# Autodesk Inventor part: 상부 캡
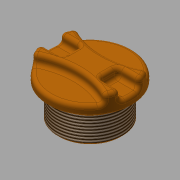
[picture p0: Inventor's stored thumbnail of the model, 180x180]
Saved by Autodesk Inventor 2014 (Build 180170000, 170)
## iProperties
Created: 2016-09
Part Number: 상부 캡
Material: ABS 플라스틱
Document SubType Name: Modeling
Designer: mduedu
Density: 1.493 g/cm^3
Appearance: 주황색
Author: mduedu
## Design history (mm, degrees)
sketch "스케치1"
  geometry: C1 r 22.5 at (0, 0); 1 further point
  constraints: 1 centre point, 1 coincident
  dimensions: "d0" = 45 diameter of C1
extrude "돌출1" new body sketch "스케치1" distance "d1" = 10; taper "d2" = 0 deg
sketch "스케치2" dims "d4" = 80
  geometry: C1 r 22.5 at (0, 0) reference; 3 further points
  constraints: 3 vertical alignment, 2 other
  dimensions: "d3" = 7 distance of point (0, 7) point (0, 0)
extrude "돌출2" cut sketch "스케치2" distance "d5" = 5; taper "d6" = 0 deg
sketch "스케치3"
  geometry: L1 (-22.5, 0)-(0, 0); L2 (-21.937, 5)-(-10, 5); L3 (-10, 5)-(-10, -5); L4 (-10, -5)-(-21.937, -5); A1 r 22.5 centre (0, 0) between (-19.118, 11.864) and (-19.118, -11.864) reference; A2 r 22.5 centre (0, 0) between (-21.937, 5) and (-21.937, -5); 1 further point
  constraints: 8 end point, 5 point on circle, 2 horizontal, 1 centre point, 1 coincident, 1 parallel, 1 perpendicular, 1 symmetric about line
  dimensions: "d7" = 10 distance from line of L3 point (0, 0); "d8" = 10 distance of L2.end L3.end
extrude "돌출3" cut sketch "스케치3" distance "d9" = 5; taper "d10" = 0 deg
fillet "모깎기1" dims "d11" = 2
fillet "모깎기2" dims "d12" = 2
fillet "모깎기3" dims "d13" = 2
sketch "스케치4"
  geometry: C1 r 17.5 at (0, 0); 1 further point
  constraints: 1 centre point, 1 coincident
  dimensions: "d14" = 35 diameter of C1
extrude "돌출4" join sketch "스케치4" distance "d15" = 17; taper "d16" = 0 deg
sketch "스케치5"
  geometry: C1 r 12.5 at (0, 0); 1 further point
  constraints: 1 centre point, 1 coincident
  dimensions: "d17" = 25 diameter of C1
extrude "돌출5" cut sketch "스케치5" distance "d18" = 10; taper "d19" = 0 deg
fillet "모깎기4" dims "d20" = 3
sketch "스케치6"
  geometry: L1 (7, 7)-(8, 7) reference; L2 (10, 5)-(10, -5) reference; L3 (8, -7)-(7, -7) reference; L4 (5, -9)-(5, -20.5) reference; L5 (3, -22.5)-(0, -22.5) reference; L6 (0, -22.5)-(0, -17.5) reference; L7 (0, -17.5)-(-17, -17.5) reference; L8 (-17, -17.5)-(-17, -12.5) reference; L9 (-17, -12.5)-(-10, -12.5) reference; L10 (-7, -9.5)-(-7, 9.5) reference; L11 (-10, 12.5)-(-17, 12.5) reference; L12 (-17, 12.5)-(-17, 17.5) reference; L13 (-17, 17.5)-(0, 17.5) reference; L14 (0, 17.5)-(0, 22.5) reference; L15 (0, 22.5)-(3, 22.5) reference; L16 (5, 20.5)-(5, 9) reference; L17 (0, -17.5)-(-2, -17.5); L18 (-2, -17.5)-(-2, -16.5); L19 (-2, -16.5)-(0, -16.5); L20 (0, -16.5)-(0, -17.5); L21 (0, 0)-(-7, 0); A1 r 2 centre (7, 9) between (5, 9) and (7, 7) reference; A2 r 2 centre (8, 5) between (10, 5) and (8, 7) reference; A3 r 2 centre (8, -5) between (8, -7) and (10, -5) reference; A4 r 2 centre (7, -9) between (7, -7) and (5, -9) reference; A5 r 2 centre (3, -20.5) between (3, -22.5) and (5, -20.5) reference; A6 r 3 centre (-10, -9.5) between (-10, -12.5) and (-7, -9.5) reference; A7 r 3 centre (-10, 9.5) between (-7, 9.5) and (-10, 12.5) reference; A8 r 2 centre (3, 20.5) between (5, 20.5) and (3, 22.5) reference
  constraints: 10 end point, 2 parallel, 1 horizontal, 1 midpoint, 1 perpendicular
  dimensions: "d26" = 2 distance of L6.end L17.end; "d27" = 1 distance of L17.end L18.end
revolve "회전1" sketch "스케치6" stored, may be unused: angle "d28" = 90 deg
feature "스레드1" dims "d21" = 10, "d22" = 0
chamfer "모따기1" distance "d23" = 1; stored, may be unused: second distance "d24" = 2, angle "d25" = 45 deg
sketch "스케치7"
  geometry: L1 (7, 7)-(8, 7) reference; L2 (10, 5)-(10, -5) reference; L3 (8, -7)-(7, -7) reference; L4 (5, -9)-(5, -20.5) reference; L5 (3, -22.5)-(0, -22.5) reference; L6 (0, -22.5)-(0, -16.5) reference; L7 (0, -16.5)-(-2, -16.5) reference; L8 (-2, -16.5)-(-3, -17.5) reference; L9 (-3, -17.5)-(-16, -17.5) reference; L10 (-16, -17.5)-(-17, -16.5) reference; L11 (-17, -16.5)-(-17, -12.5) reference; L12 (-17, -12.5)-(-10, -12.5) reference; L13 (-7, -9.5)-(-7, 9.5) reference; L14 (-10, 12.5)-(-17, 12.5) reference; L15 (-17, 12.5)-(-17, 16.5) reference; L16 (-17, 16.5)-(-16, 17.5) reference; L17 (-16, 17.5)-(-3, 17.5) reference; L18 (-3, 17.5)-(-2, 16.5) reference; L19 (-2, 16.5)-(0, 16.5) reference; L20 (0, 16.5)-(0, 22.5) reference; L21 (0, 22.5)-(3, 22.5) reference; L22 (5, 20.5)-(5, 9) reference; L23 (0, -22.5)-(1, -22.5); L24 (1, -22.5)-(1, -21.5); L25 (1, -21.5)-(0, -21.5); L26 (0, -21.5)-(0, -22.5); L27 (0, 0)-(-7, 0); A1 r 2 centre (7, 9) between (5, 9) and (7, 7) reference; A2 r 2 centre (8, 5) between (10, 5) and (8, 7) reference; A3 r 2 centre (8, -5) between (8, -7) and (10, -5) reference; A4 r 2 centre (7, -9) between (7, -7) and (5, -9) reference; A5 r 2 centre (3, -20.5) between (3, -22.5) and (5, -20.5) reference; A6 r 3 centre (-10, -9.5) between (-10, -12.5) and (-7, -9.5) reference; A7 r 3 centre (-10, 9.5) between (-7, 9.5) and (-10, 12.5) reference; A8 r 2 centre (3, 20.5) between (5, 20.5) and (3, 22.5) reference
  constraints: 10 end point, 2 parallel, 1 horizontal, 1 midpoint, 1 perpendicular
  dimensions: "d29" = 1 distance of L25.end L24.end; "d30" = 1 distance of L24.end L23.end
revolve "회전2" sketch "스케치7" stored, may be unused: angle "d31" = 90 deg
node "솔리드1"
mirror "대칭1"
mirror "대칭2"
node "투영된 루프1"
node "절단 모서리 투영1"
node "절단 모서리 투영2"
